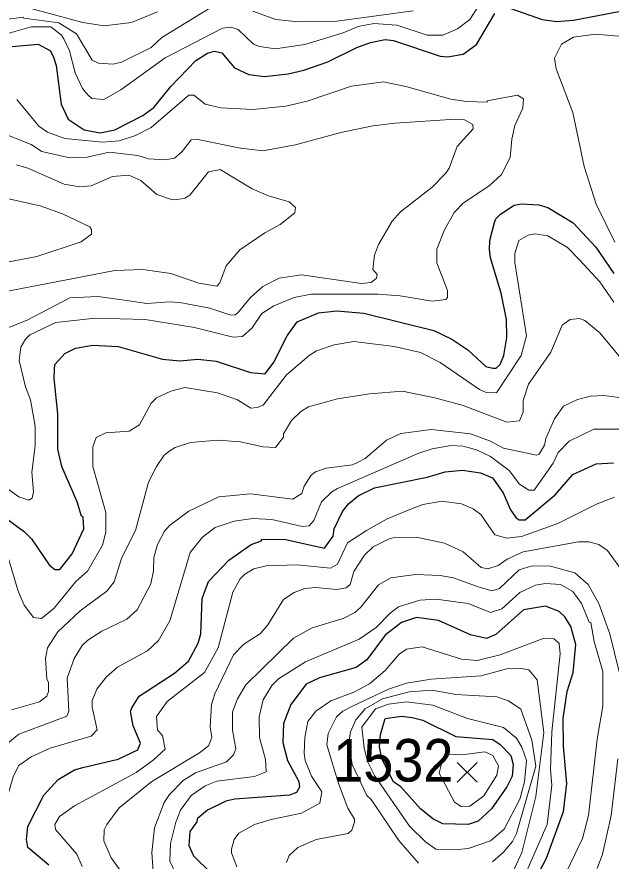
# Model space of a CAD drawing. Extents: x 423 to 448.8, y 7456.3 to 7484.
# Drawn here: x 434.372 to 435.491, y 7474.202 to 7475.791 of the extents above; entities that cross this region are included whole.
import ezdxf
from ezdxf.enums import TextEntityAlignment as Align

# ---------------------------------------------------------------- set-up
doc = ezdxf.new("R2010")
doc.units = 0
doc.header["$LTSCALE"] = 0.032
for name, color, linetype, lineweight in [('1', 7, 'Continuous', 25), ('2', 7, 'Continuous', 13), ('21', 7, 'Continuous', 25)]:
    doc.layers.add(name, color=color, linetype=linetype, lineweight=lineweight)
doc.layers.add('61', color=7, linetype='Continuous')

msp = doc.modelspace()

# ---------------------------------------------------------------- linework, layer by layer
at = {"layer": '1'}
for points in [[(435.3027, 7475.8073), (435.3615, 7475.7864), (435.3893, 7475.7825), (435.4203, 7475.7849), (435.5518, 7475.8104)], [(434.7443, 7475.7268), (434.7582, 7475.7238), (434.7821, 7475.6952), (434.8092, 7475.6828), (434.8386, 7475.6789), (434.8835, 7475.6843), (434.9129, 7475.6913), (434.9577, 7475.7067), (435.0126, 7475.7338), (435.0381, 7475.7431), (435.066, 7475.7485), (435.0815, 7475.747), (435.1697, 7475.7176), (435.1836, 7475.716), (435.213, 7475.7214), (435.2377, 7475.7392), (435.2725, 7475.798)], [(434.3637, 7475.7354), (434.4124, 7475.74), (434.4356, 7475.7276), (434.4411, 7475.7153), (434.4465, 7475.6998), (434.4558, 7475.6271), (434.4689, 7475.5985), (434.4991, 7475.5784), (434.5292, 7475.573), (434.5571, 7475.5784), (434.6096, 7475.6054), (434.6306, 7475.6209), (434.6623, 7475.6603), (434.7095, 7475.7091), (434.7311, 7475.723), (434.7443, 7475.7268)], [(434.4441, 7474.7507), (434.4534, 7474.7507), (434.4766, 7474.7802), (434.4983, 7474.8273), (434.4975, 7474.8498), (434.4944, 7474.8513), (434.4859, 7474.8784), (434.4573, 7474.9449), (434.4496, 7474.9774), (434.4496, 7475.0439), (434.4426, 7475.1104), (434.4434, 7475.1275), (434.4441, 7475.1367), (434.4627, 7475.1576), (434.4828, 7475.1677), (434.5153, 7475.1731), (434.5633, 7475.1708), (434.6468, 7475.1468), (434.6793, 7475.1437), (434.7133, 7475.1467), (434.7474, 7475.1429), (434.8123, 7475.122), (434.8402, 7475.1189), (434.8564, 7475.1414), (434.8811, 7475.1909), (434.9005, 7475.2172), (434.9407, 7475.2342), (434.9748, 7475.238), (435.0258, 7475.2334), (435.1573, 7475.2009), (435.1913, 7475.1847), (435.2215, 7475.1646), (435.2555, 7475.1329), (435.2687, 7475.1297), (435.2748, 7475.1297), (435.2826, 7475.1367), (435.2895, 7475.1537), (435.295, 7475.1878), (435.2942, 7475.2218), (435.2841, 7475.2713), (435.264, 7475.3378), (435.2625, 7475.3533), (435.2632, 7475.3703), (435.2718, 7475.4043), (435.2741, 7475.4113), (435.2833, 7475.4198), (435.3088, 7475.4368), (435.3228, 7475.4391), (435.3553, 7475.4376), (435.3723, 7475.4322), (435.4202, 7475.4035), (435.4628, 7475.3579), (435.4968, 7475.3084)], [(434.4325, 7474.1939), (434.3931, 7474.2271), (434.3908, 7474.2426), (434.3931, 7474.2666), (434.4232, 7474.3261), (434.4503, 7474.3555), (434.4812, 7474.3733), (434.4968, 7474.378), (434.5633, 7474.3934), (434.6004, 7474.4112), (434.605, 7474.4236), (434.5911, 7474.4561), (434.5864, 7474.4831), (434.5888, 7474.4901), (434.6027, 7474.5125), (434.6692, 7474.5558), (434.6955, 7474.5783), (434.7141, 7474.6123), (434.7187, 7474.6293), (434.7211, 7474.6959), (434.7334, 7474.7283), (434.7713, 7474.7685), (434.8138, 7474.7979), (434.8332, 7474.8049), (434.8332, 7474.8072), (434.8758, 7474.808), (434.9515, 7474.791), (434.9678, 7474.8134), (434.9701, 7474.8273), (434.9856, 7474.8598), (434.9972, 7474.8745), (435.015, 7474.8892), (435.0459, 7474.9047), (435.1449, 7474.9248), (435.179, 7474.9348), (435.2114, 7474.9379), (435.2455, 7474.9325), (435.2679, 7474.9233), (435.288, 7474.8954), (435.3019, 7474.8629), (435.3127, 7474.8482), (435.3184, 7474.8444), (435.3184, 7474.8445), (435.3298, 7474.8444), (435.3862, 7474.8915), (435.4195, 7474.9294), (435.4636, 7474.9495), (435.4961, 7474.9518)], [(434.3188, 7474.8714), (434.3869, 7474.8219), (434.4, 7474.8087), (434.4333, 7474.7593), (434.4441, 7474.7507)], [(435.3421, 7474.1544), (435.37, 7474.207), (435.4017, 7474.2952), (435.4079, 7474.3478), (435.4017, 7474.4174), (435.4009, 7474.47), (435.4086, 7474.5211), (435.4202, 7474.5566), (435.4249, 7474.6092), (435.4156, 7474.6433), (435.404, 7474.6618), (435.3939, 7474.6719), (435.3677, 7474.6819), (435.3267, 7474.675), (435.2741, 7474.6285), (435.257, 7474.6208), (435.2269, 7474.6278), (435.1666, 7474.6549), (435.1248, 7474.6603), (435.097, 7474.651), (435.066, 7474.627), (435.0312, 7474.5806), (435.0111, 7474.5659), (434.9423, 7474.5465), (434.9175, 7474.535), (434.8881, 7474.4963), (434.8742, 7474.4607), (434.8734, 7474.4251), (434.8819, 7474.3911), (434.9036, 7474.3516), (434.9044, 7474.3408), (434.8989, 7474.3308), (434.8858, 7474.3261), (434.7829, 7474.3184), (434.7659, 7474.3145), (434.7311, 7474.2975), (434.7118, 7474.2812), (434.711, 7474.2758), (434.6979, 7474.2573), (434.6963, 7474.231), (434.7048, 7474.2116), (434.7388, 7474.1784)]]:
    msp.add_lwpolyline(points, dxfattribs=at)
msp.add_lwpolyline([(435.066, 7474.47), (435.097, 7474.4746), (435.1171, 7474.4723), (435.1372, 7474.4669), (435.1991, 7474.436), (435.2687, 7474.4305), (435.2826, 7474.4212), (435.3027, 7474.4004), (435.3073, 7474.3834), (435.305, 7474.3617), (435.2949, 7474.3416), (435.2663, 7474.2998), (435.2408, 7474.2766), (435.2223, 7474.2704), (435.1743, 7474.272), (435.1557, 7474.2813), (435.1325, 7474.2998), (435.0954, 7474.3416), (435.0817, 7474.3507), (435.0594, 7474.3942), (435.055, 7474.4165), (435.0572, 7474.4399)], close=True, dxfattribs=at)
at = {"layer": '2'}
for points in [[(434.2075, 7475.798), (434.2817, 7475.7833), (434.3251, 7475.7833), (434.3846, 7475.7911), (434.3854, 7475.7887), (434.4517, 7475.7799), (434.4847, 7475.7596), (434.5145, 7475.7098), (434.5262, 7475.7044), (434.554, 7475.7021), (434.5695, 7475.706), (434.6252, 7475.7338), (434.6453, 7475.7524), (434.7605, 7475.8228)], [(435.7946, 7475.8251), (435.7722, 7475.7833), (435.7528, 7475.7616), (435.7381, 7475.7508), (435.7003, 7475.7361), (435.6678, 7475.7331), (435.5347, 7475.7524), (435.462, 7475.7586), (435.4203, 7475.7531), (435.3978, 7475.74), (435.3847, 7475.7137), (435.3878, 7475.6936), (435.4195, 7475.6116)], [(434.3421, 7475.7562), (434.3993, 7475.7725), (434.4364, 7475.7725), (434.4565, 7475.757), (434.4611, 7475.7501), (434.4712, 7475.7277), (434.482, 7475.6859), (434.496, 7475.6565), (434.5068, 7475.6441), (434.5138, 7475.6379), (434.5362, 7475.6356), (434.5679, 7475.6542), (434.6515, 7475.7145), (434.7597, 7475.7702), (434.7752, 7475.7717), (434.7891, 7475.7678), (434.8177, 7475.74), (434.8294, 7475.7353), (434.8587, 7475.7315), (434.9144, 7475.7392), (434.9871, 7475.7616), (435.015, 7475.7733), (435.0444, 7475.7787), (435.0877, 7475.7756), (435.1449, 7475.757), (435.1743, 7475.757), (435.2022, 7475.7686), (435.2254, 7475.7864), (435.2423, 7475.8127)], [(434.6375, 7475.8011), (434.588, 7475.781), (434.537, 7475.7748), (434.4968, 7475.781), (434.3916, 7475.8088)], [(434.817, 7475.8019), (434.8603, 7475.7864), (434.9021, 7475.7818), (434.9748, 7475.7833), (435.1186, 7475.8026)], [(434.3722, 7475.6356), (434.414, 7475.5853), (434.4302, 7475.5745), (434.4627, 7475.5621), (434.5339, 7475.5552), (434.5648, 7475.5582), (434.5958, 7475.5683), (434.6252, 7475.583), (434.6963, 7475.6441), (434.7056, 7475.6441), (434.7272, 7475.6271), (434.735, 7475.6248), (434.7566, 7475.6201), (434.817, 7475.617), (434.8789, 7475.6232), (434.9191, 7475.6325), (435.0026, 7475.6611), (435.0629, 7475.6689), (435.1047, 7475.6603), (435.1898, 7475.6364), (435.2192, 7475.6317), (435.2578, 7475.631), (435.2578, 7475.6333), (435.315, 7475.6441), (435.3267, 7475.6371), (435.3251, 7475.6194), (435.3104, 7475.5869), (435.3042, 7475.5613), (435.3012, 7475.5266), (435.2849, 7475.4948), (435.2617, 7475.4732), (435.2137, 7475.4414), (435.196, 7475.4229), (435.1774, 7475.3904), (435.1635, 7475.3541), (435.1635, 7475.3285), (435.1836, 7475.276), (435.1836, 7475.2628), (435.1805, 7475.2589), (435.1542, 7475.2558), (435.0939, 7475.2659), (435.0521, 7475.269), (434.9268, 7475.269), (434.8943, 7475.2628), (434.8564, 7475.2473), (434.834, 7475.2326), (434.8154, 7475.2055), (434.7976, 7475.1893), (434.7798, 7475.1885), (434.7071, 7475.2063), (434.6143, 7475.2218), (434.52, 7475.2241), (434.4457, 7475.2156), (434.397, 7475.1924), (434.3884, 7475.1846), (434.3799, 7475.1692), (434.3769, 7475.1445), (434.3885, 7475.095), (434.3978, 7475.0702), (434.407, 7475.0207), (434.407, 7474.9836), (434.4008, 7474.9341), (434.4039, 7474.897), (434.4009, 7474.8853), (434.3947, 7474.8814), (434.3761, 7474.8876), (434.3498, 7474.9062)], [(435.4195, 7475.6116), (435.4404, 7475.5095), (435.4635, 7475.4384), (435.4984, 7475.3672)], [(434.3374, 7475.5753), (434.3993, 7475.5513), (434.4194, 7475.5381), (434.472, 7475.5258), (434.5045, 7475.5273), (434.5463, 7475.5366), (434.6004, 7475.5304), (434.6205, 7475.5242), (434.6515, 7475.5219), (434.6692, 7475.525), (434.6839, 7475.5381), (434.7009, 7475.5598), (434.7102, 7475.5613), (434.7938, 7475.5443), (434.8355, 7475.5389), (434.8974, 7475.5505), (434.9825, 7475.5737), (435.0428, 7475.5861), (435.0846, 7475.5915), (435.1975, 7475.5985), (435.2153, 7475.5977), (435.2308, 7475.5884), (435.2315, 7475.5807), (435.2014, 7475.5474), (435.1867, 7475.5064), (435.1805, 7475.4972), (435.1542, 7475.4708), (435.0946, 7475.4245), (435.0792, 7475.4066), (435.0536, 7475.3626), (435.0459, 7475.3425), (435.0428, 7475.3154), (435.0506, 7475.3061), (435.0498, 7475.2992), (435.0397, 7475.2914), (435.0212, 7475.2891), (434.9082, 7475.3053), (434.8665, 7475.2992), (434.8355, 7475.2837), (434.8123, 7475.2628), (434.7883, 7475.2341), (434.7837, 7475.2303), (434.7752, 7475.2295), (434.7357, 7475.2427), (434.6793, 7475.2535), (434.6592, 7475.255), (434.6174, 7475.2519), (434.5664, 7475.2589), (434.5246, 7475.2651), (434.472, 7475.262), (434.3916, 7475.2202), (434.3111, 7475.1885)], [(434.3715, 7475.5126), (434.3931, 7475.5064), (434.4612, 7475.4762), (434.4906, 7475.4716), (434.5122, 7475.4732), (434.5525, 7475.491), (434.5834, 7475.4933), (434.6058, 7475.4832), (434.6359, 7475.4569), (434.6654, 7475.4469), (434.6747, 7475.4476), (434.6886, 7475.45), (434.6979, 7475.4554), (434.7334, 7475.4995), (434.7551, 7475.5041), (434.8154, 7475.4678), (434.8464, 7475.4546), (434.885, 7475.443), (434.8974, 7475.4321), (434.8958, 7475.4221), (434.868, 7475.4004), (434.8394, 7475.385), (434.7922, 7475.3525), (434.7667, 7475.3224), (434.7543, 7475.2906), (434.7489, 7475.2844), (434.7149, 7475.2899), (434.6623, 7475.3084), (434.6097, 7475.3154), (434.5571, 7475.3138), (434.4627, 7475.2953), (434.3483, 7475.2736)], [(434.3544, 7475.3293), (434.4101, 7475.3401), (434.4937, 7475.368), (434.513, 7475.3819), (434.513, 7475.3912), (434.5099, 7475.3958), (434.4581, 7475.4206), (434.4163, 7475.4353), (434.3452, 7475.4515)], [(435.4968, 7475.2543), (435.4705, 7475.2922), (435.4318, 7475.3339), (435.4094, 7475.3572), (435.3723, 7475.3788), (435.3476, 7475.3827), (435.3352, 7475.3803), (435.3174, 7475.3703), (435.3104, 7475.3456), (435.3104, 7475.3286), (435.3321, 7475.1909), (435.322, 7475.1537), (435.2756, 7475.0833), (435.2563, 7475.0841), (435.2439, 7475.0895), (435.1697, 7475.1406), (435.1325, 7475.1591), (435.083, 7475.1708), (435.0072, 7475.18), (434.9701, 7475.1739), (434.9368, 7475.1622), (434.9229, 7475.1537), (434.8804, 7475.1174), (434.8363, 7475.0601), (434.8247, 7475.0555), (434.8131, 7475.0547), (434.7876, 7475.0702), (434.7505, 7475.0833), (434.6886, 7475.0934), (434.6623, 7475.0864), (434.6352, 7475.0741), (434.6251, 7475.064), (434.6035, 7475.023), (434.5841, 7475.0114), (434.5401, 7475.0083), (434.5215, 7474.999), (434.5153, 7474.982), (434.5153, 7474.9449), (434.5401, 7474.8583), (434.5401, 7474.8212), (434.5339, 7474.7964), (434.5052, 7474.7477), (434.4836, 7474.7283), (434.4426, 7474.678), (434.4186, 7474.6587), (434.4039, 7474.6602), (434.3861, 7474.6835), (434.3746, 7474.7098), (434.356, 7474.7732)], [(434.3621, 7474.4862), (434.4148, 7474.5017), (434.4287, 7474.5125), (434.4318, 7474.5211), (434.4318, 7474.538), (434.4287, 7474.545), (434.4263, 7474.5829), (434.4302, 7474.603), (434.4496, 7474.6332), (434.4913, 7474.6726), (434.5416, 7474.7097), (434.5555, 7474.7275), (434.5702, 7474.7732), (434.5957, 7474.8243), (434.6205, 7474.9155), (434.6352, 7474.9449), (434.6499, 7474.9658), (434.6607, 7474.9743), (434.6708, 7474.9805), (434.6994, 7474.9898), (434.7505, 7474.9944), (434.7938, 7474.9913), (434.8355, 7474.982), (434.8595, 7474.9805), (434.8742, 7474.9998), (434.8742, 7475.006), (434.8896, 7475.0315), (434.9074, 7475.0485), (434.9214, 7475.057), (434.9763, 7475.0718), (435.0366, 7475.0818), (435.0985, 7475.0864), (435.1619, 7475.0733), (435.213, 7475.0594), (435.295, 7475.0284), (435.3189, 7475.0307), (435.3259, 7475.047), (435.3259, 7475.0687), (435.3359, 7475.0996), (435.3777, 7475.1599), (435.3994, 7475.211), (435.4141, 7475.2218), (435.4318, 7475.2234), (435.4419, 7475.2195), (435.4705, 7475.1963), (435.5192, 7475.1375)], [(434.9136, 7474.9077), (434.9268, 7474.9286), (434.9345, 7474.9348), (434.9547, 7474.9418), (435.0042, 7474.948), (435.0165, 7474.9534), (435.0281, 7474.9596), (435.0683, 7474.9944), (435.0954, 7475.0068), (435.1527, 7475.0145), (435.2269, 7475.006), (435.264, 7474.9921), (435.2888, 7474.9789), (435.3507, 7474.9658), (435.356, 7474.9681), (435.3661, 7474.9851), (435.3684, 7474.9975), (435.3847, 7475.0346), (435.4017, 7475.0586), (435.428, 7475.071), (435.4528, 7475.0771), (435.4775, 7475.0787), (435.5061, 7475.0748)], [(434.639, 7474.617), (434.6607, 7474.6541), (434.6986, 7474.7825), (434.7218, 7474.8119), (434.7458, 7474.8296), (434.7814, 7474.842), (434.817, 7474.8467), (434.8526, 7474.8451), (434.9098, 7474.832), (434.9229, 7474.8327), (434.9314, 7474.8428), (434.9461, 7474.8784), (434.9655, 7474.8969), (434.9763, 7474.9031), (435.1295, 7474.9696), (435.1542, 7474.9781), (435.1898, 7474.9843), (435.213, 7474.9828), (435.2377, 7474.9758), (435.264, 7474.9635), (435.2996, 7474.9371), (435.3189, 7474.9116), (435.3367, 7474.9), (435.3468, 7474.9), (435.3823, 7474.9511), (435.3916, 7474.9712), (435.4125, 7474.9921), (435.4589, 7475.0153), (435.5069, 7475.0153)], [(434.3552, 7474.4236), (434.3761, 7474.4406), (434.4666, 7474.4746), (434.4705, 7474.4839), (434.4674, 7474.5458), (434.4805, 7474.5829), (434.4952, 7474.6077), (434.506, 7474.6177), (434.5323, 7474.6347), (434.5795, 7474.6571), (434.5989, 7474.675), (434.6244, 7474.7237), (434.6298, 7474.7485), (434.6305, 7474.7732), (434.6375, 7474.798), (434.6507, 7474.8227), (434.6599, 7474.8335), (434.6963, 7474.8606), (434.7527, 7474.8876), (434.8123, 7474.8931), (434.892, 7474.883), (434.909, 7474.8939), (434.9136, 7474.9077)], [(434.9763, 7474.7608), (434.9948, 7474.8011), (435.0305, 7474.8242), (435.0699, 7474.8459), (435.1124, 7474.8637), (435.1372, 7474.8729), (435.1728, 7474.8791), (435.2099, 7474.8745), (435.2316, 7474.8652), (435.2462, 7474.8544), (435.2725, 7474.8157), (435.295, 7474.8095), (435.3228, 7474.8126), (435.3909, 7474.8374), (435.4651, 7474.8745), (435.4976, 7474.8869)], [(435.5154, 7474.7438), (435.4845, 7474.7863), (435.4682, 7474.798), (435.4497, 7474.8026), (435.4303, 7474.8026), (435.3259, 7474.784), (435.2957, 7474.7701), (435.2787, 7474.7585), (435.2594, 7474.7523), (435.247, 7474.7546), (435.2129, 7474.784), (435.1774, 7474.8002), (435.1248, 7474.8119), (435.083, 7474.8111), (435.0722, 7474.808), (435.0436, 7474.7933), (435.0273, 7474.7778), (435.0072, 7474.7469), (435.0003, 7474.7222), (434.9925, 7474.7159), (434.9748, 7474.7128), (434.9345, 7474.7167), (434.9144, 7474.7152), (434.8943, 7474.7074), (434.8742, 7474.6943), (434.8448, 7474.6464), (434.8309, 7474.6301), (434.7999, 7474.61), (434.7806, 7474.5899), (434.745, 7474.5164), (434.7388, 7474.4963), (434.7365, 7474.4545), (434.7396, 7474.4344), (434.7334, 7474.4189), (434.7164, 7474.4058), (434.6267, 7474.3516), (434.5648, 7474.3022), (434.5416, 7474.2705), (434.537, 7474.2604), (434.5362, 7474.2395), (434.5501, 7474.2078), (434.5748, 7474.173)], [(434.4952, 7474.1916), (434.4851, 7474.2148), (434.4449, 7474.2612), (434.4442, 7474.2704), (434.4527, 7474.2859), (434.4812, 7474.306), (434.5973, 7474.3687), (434.629, 7474.3919), (434.6514, 7474.4127), (434.6468, 7474.4383), (434.6375, 7474.4483), (434.6352, 7474.4739), (434.6553, 7474.5024), (434.7257, 7474.5566), (434.7512, 7474.603), (434.779, 7474.7082), (434.793, 7474.733), (434.8015, 7474.7422), (434.8185, 7474.7523), (434.8417, 7474.7577), (434.9005, 7474.7593), (434.9631, 7474.7531), (434.9763, 7474.7608)], [(435.5069, 7474.5582), (435.4891, 7474.6293), (435.4682, 7474.6866), (435.4481, 7474.7222), (435.4233, 7474.7446), (435.377, 7474.7569), (435.3429, 7474.7577), (435.3182, 7474.75), (435.281, 7474.7152), (435.2671, 7474.7105), (435.2408, 7474.7183), (435.1944, 7474.7353), (435.1697, 7474.7392), (435.1233, 7474.7415), (435.0769, 7474.7353), (435.0537, 7474.7221), (435.0204, 7474.6796), (435.0087, 7474.6695), (434.9871, 7474.6587), (434.9284, 7474.6409), (434.8935, 7474.6216), (434.8038, 7474.5334), (434.7876, 7474.5071), (434.7783, 7474.4824), (434.7783, 7474.4484), (434.7845, 7474.4128), (434.7806, 7474.4019), (434.7674, 7474.3888), (434.7087, 7474.3679), (434.6854, 7474.3532), (434.6599, 7474.3269), (434.6499, 7474.3122), (434.6313, 7474.2643), (434.6267, 7474.2179), (434.629, 7474.1823)], [(435.4087, 7474.1838), (435.4373, 7474.2442), (435.4489, 7474.2875), (435.4651, 7474.4313), (435.476, 7474.4932), (435.476, 7474.5589), (435.4597, 7474.6154), (435.4535, 7474.651), (435.4504, 7474.6517), (435.4357, 7474.6866), (435.4195, 7474.709), (435.3963, 7474.7222), (435.3677, 7474.7245), (435.3491, 7474.7214), (435.3197, 7474.7074), (435.2857, 7474.6765), (435.264, 7474.6696), (435.2223, 7474.6865), (435.1619, 7474.6951), (435.131, 7474.6927), (435.0908, 7474.6803), (435.0753, 7474.6688), (435.049, 7474.6417), (435.0173, 7474.6193), (434.916, 7474.5767), (434.8649, 7474.545), (434.8526, 7474.5326), (434.8363, 7474.5056), (434.8285, 7474.4731), (434.8293, 7474.4344), (434.8409, 7474.3927), (434.8417, 7474.3695), (434.8201, 7474.3609), (434.7489, 7474.3524), (434.7273, 7474.3431), (434.7009, 7474.3253), (434.6808, 7474.2975), (434.6715, 7474.2751), (434.6615, 7474.2349), (434.6607, 7474.2016), (434.6723, 7474.1761)], [(434.3366, 7474.173), (434.3359, 7474.221), (434.3475, 7474.2565), (434.3521, 7474.2797), (434.3521, 7474.3153), (434.366, 7474.3625), (434.3761, 7474.3818), (434.3993, 7474.3981), (434.4349, 7474.4143), (434.5122, 7474.4367), (434.5238, 7474.4491), (434.5145, 7474.4917), (434.5145, 7474.504), (434.523, 7474.5257), (434.5408, 7474.5481), (434.5617, 7474.5667), (434.6182, 7474.5976), (434.639, 7474.617)], [(435.3197, 7474.1529), (435.3708, 7474.2705), (435.38, 7474.3447), (435.377, 7474.3741), (435.38, 7474.4453), (435.3955, 7474.5922), (435.3939, 7474.6115), (435.3839, 7474.62), (435.3638, 7474.6208), (435.2826, 7474.5899), (435.2393, 7474.5791), (435.2099, 7474.5821), (435.1356, 7474.6053), (435.1062, 7474.6007), (435.0923, 7474.5914), (435.066, 7474.5605), (435.0366, 7474.5357), (435.0072, 7474.5195), (434.9639, 7474.5032), (434.9353, 7474.4839), (434.9206, 7474.4646), (434.9144, 7474.4344), (434.9136, 7474.405), (434.9152, 7474.3911), (434.9275, 7474.3617), (434.9469, 7474.3323), (434.943, 7474.3106), (434.9082, 7474.2921), (434.851, 7474.2797), (434.8201, 7474.2705), (434.7907, 7474.2542), (434.7814, 7474.2426), (434.7767, 7474.224), (434.7767, 7474.2171), (434.7868, 7474.1908)], [(434.8804, 7474.1993), (434.885, 7474.2124), (434.9013, 7474.2271), (434.9361, 7474.2426), (434.9964, 7474.2534), (435.0034, 7474.2596), (435.008, 7474.2751), (435.008, 7474.2805), (434.9956, 7474.3014), (434.9778, 7474.3478), (434.9562, 7474.4205), (434.9585, 7474.4422), (434.974, 7474.4731), (434.9863, 7474.4839), (435.0042, 7474.4932), (435.0722, 7474.5257), (435.1062, 7474.5365), (435.1527, 7474.5443), (435.247, 7474.5504), (435.295, 7474.5636), (435.3182, 7474.5651), (435.3367, 7474.562), (435.3522, 7474.5427), (435.3646, 7474.4437), (435.3499, 7474.3231), (435.3236, 7474.2179), (435.3073, 7474.1823)], [(435.2679, 7474.2), (435.288, 7474.2178), (435.3058, 7474.2387), (435.3135, 7474.2534), (435.3496, 7474.3805), (435.3421, 7474.4292), (435.3212, 7474.4878), (435.2981, 7474.5032), (435.2764, 7474.511), (435.1991, 7474.5156), (435.1542, 7474.5233), (435.1109, 7474.5203), (435.0612, 7474.5074), (435.0282, 7474.4886), (435.0109, 7474.4676), (435.0004, 7474.4451), (434.9974, 7474.4241), (435.0041, 7474.3836), (435.0312, 7474.3253), (435.0397, 7474.3176), (435.0915, 7474.2403), (435.1286, 7474.1977)], [(435.4651, 7474.1877), (435.4752, 7474.2148), (435.4914, 7474.2875), (435.5038, 7474.3942)]]:
    msp.add_lwpolyline(points, dxfattribs=at)
for points in [[(435.2037, 7474.2232), (435.2223, 7474.2256), (435.264, 7474.2395), (435.2903, 7474.2619), (435.3197, 7474.3184), (435.3282, 7474.3509), (435.3321, 7474.3911), (435.3236, 7474.4159), (435.3135, 7474.4329), (435.2887, 7474.453), (435.2207, 7474.47), (435.1558, 7474.4955), (435.1062, 7474.5017), (435.0722, 7474.497), (435.0475, 7474.4885), (435.0219, 7474.4537), (435.0262, 7474.4147), (435.0325, 7474.3889), (435.046, 7474.3629), (435.1116, 7474.2673), (435.1418, 7474.2379), (435.1611, 7474.224)], [(435.1967, 7474.3126), (435.1676, 7474.3674), (435.173, 7474.39), (435.1864, 7474.4029), (435.2104, 7474.4019), (435.2539, 7474.4073), (435.2687, 7474.4004), (435.2795, 7474.381), (435.2764, 7474.3632), (435.2516, 7474.3246), (435.2253, 7474.3052), (435.2091, 7474.3045)]]:
    msp.add_lwpolyline(points, close=True, dxfattribs=at)
at = {"layer": '21'}
for p, q in [((435.2016, 7474.3876), (435.2391, 7474.3501)), ((435.2391, 7474.3876), (435.2016, 7474.3501))]:
    msp.add_line(p, q, dxfattribs=at)

# ---------------------------------------------------------------- texts
at = {"layer": '61', "width": 0.95}
msp.add_text('1532', height=0.08, dxfattribs=at).set_placement((435.0813, 7474.3515), align=Align.CENTER)

doc.saveas('drawing.dxf')
